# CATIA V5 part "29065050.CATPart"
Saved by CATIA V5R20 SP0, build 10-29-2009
Part number: 29065050
Definition: NONE
Nomenclature: 29065050
Source: Unknown
Description: 29065050
Bounding box of the stored display mesh (mm): x -25 to 44.548, y -46.5 to 81.048, z -36.5 to 36.5
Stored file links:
  C:\Users\Utente\Desktop\IO LAVORO\3D X SITO CF\X SITO\PLASTICA\RF1\29065050.CATPart
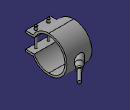
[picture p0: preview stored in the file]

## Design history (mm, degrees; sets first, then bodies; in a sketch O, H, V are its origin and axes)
Body1 "29065050" (main body)
  Solid1: solid without history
